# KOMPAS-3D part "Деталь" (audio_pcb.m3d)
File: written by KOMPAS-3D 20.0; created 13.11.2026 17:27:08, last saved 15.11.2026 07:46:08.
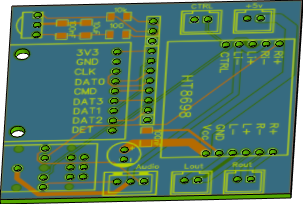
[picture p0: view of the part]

Document properties: Полное имя файла: D:\myProjects\Progect_esp32\box_compas\аудио\audio_pcb.m3d

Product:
- Part/product: Деталь
    Масса: 0.0248425

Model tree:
1. Эскиз:1
2. Элемент выдавливания:1
     Расстояние 1 = 1.2
3. Эскиз:2  (with: Элемент выдавливания:1)
4. Элемент выдавливания:2
     Расстояние 2 = 1.2
5. Эскиз:3  (with: Элемент выдавливания:1)
6. Элемент выдавливания:3
     Расстояние 2 = 1.2
7. Массив по сетке:1  (with: Элемент выдавливания:3, Эскиз:3)  (9 pattern instances)
     Шаг 1 = 10; Угол раствора = -90; Шаг 2 = 2.54
8. Эскиз:4  (with: Элемент выдавливания:1)
9. Элемент выдавливания:4
     Расстояние 2 = 1.2
10. Эскиз:5  (with: Элемент выдавливания:1, Элемент выдавливания:4)
11. Элемент выдавливания:5
     Расстояние 2 = 1.2
12. Массив по сетке:2  (with: Элемент выдавливания:5, Эскиз:5)  (6 pattern instances)
     Шаг 1 = 2.5; Угол раствора = -90; Шаг 2 = 2.5
13. Эскиз:6  (with: Элемент выдавливания:1, Элемент выдавливания:2, Элемент выдавливания:4)
14. Эскиз:8  (with: Элемент выдавливания:1, Элемент выдавливания:3)
15. Элемент выдавливания:6
     Расстояние 2 = 1.2
16. Массив по сетке:3  (with: Элемент выдавливания:6, Эскиз:8)  (8 pattern instances)
     Шаг 1 = 10; Угол раствора = -90; Шаг 2 = 2.54
17. Эскиз:9  (with: Элемент выдавливания:1, Элемент выдавливания:6)
18. Элемент выдавливания:7
     Расстояние 2 = 1.2
19. Массив по сетке:4  (with: Элемент выдавливания:7, Эскиз:9)  (5 pattern instances)
     Шаг 1 = 2.54; Угол раствора = 90
20. Эскиз:10  (with: Элемент выдавливания:1, Элемент выдавливания:7)
21. Элемент выдавливания:8
     Расстояние 2 = 1.2
22. Массив по сетке:5  (with: Элемент выдавливания:8, Эскиз:10)  (6 pattern instances)
     Шаг 1 = 2.54; Угол раствора = 90
23. Эскиз:11  (with: Элемент выдавливания:1, Элемент выдавливания:6)
24. Элемент выдавливания:9
     Расстояние 2 = 1.2
25. Массив по сетке:6  (with: Элемент выдавливания:9, Эскиз:11)  (2 pattern instances)
     Шаг 1 = 2.54; Угол раствора = 90
26. Эскиз:12  (with: Элемент выдавливания:1, Элемент выдавливания:9)
27. Элемент выдавливания:10
     Расстояние 2 = 1.2
28. Массив по сетке:7  (with: Элемент выдавливания:10, Эскиз:12)  (3 pattern instances)
     Шаг 1 = 2.54; Угол раствора = 90
29. Эскиз:13  (with: Элемент выдавливания:1, Элемент выдавливания:9)
30. Элемент выдавливания:11
     Расстояние 2 = 1.2
31. Массив по сетке:8  (with: Элемент выдавливания:11, Эскиз:13)  (3 pattern instances)
     Шаг 1 = 10; Угол раствора = -90; Шаг 2 = 2.54
32. Эскиз:15  (with: Элемент выдавливания:1)
33. Элемент выдавливания:12
     Расстояние 2 = 1.2
34. Массив по сетке:9  (with: Элемент выдавливания:12, Эскиз:15)  (2 pattern instances)
     Шаг 1 = 10; Угол раствора = -90; Шаг 2 = 2.5

Referenced files in D:\myProjects\Progect_esp32\box_compas\аудио\: audio_pcb v2 50 55.png
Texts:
  audio_pcb v2 50 55.png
